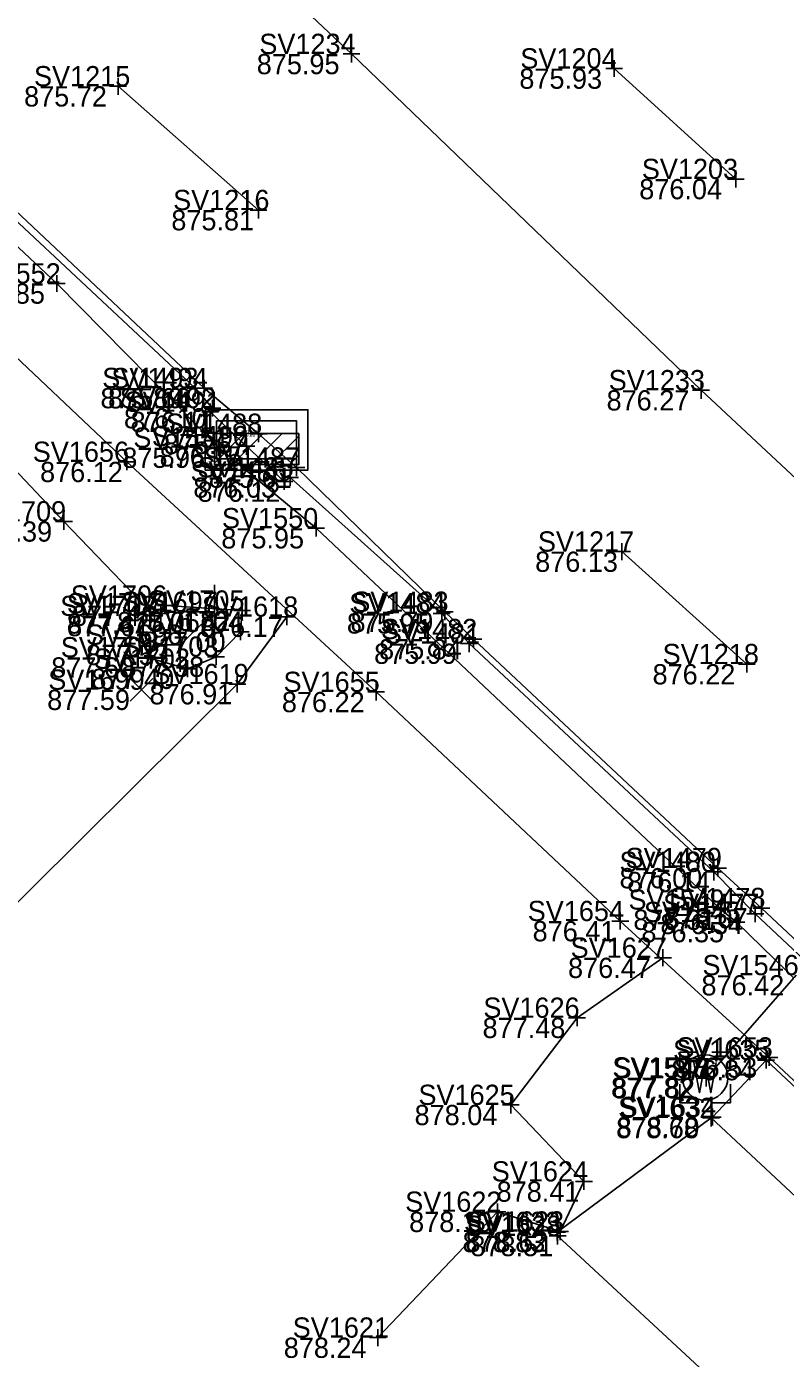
# Model space of a CAD drawing. Extents: x 1480001 to 1480402, y 379235 to 379603.
# Drawn here: x 1480223.3 to 1480268.3, y 379281.8 to 379360.8 of the extents above; entities that cross this region are included whole.
import ezdxf

# ---------------------------------------------------------------- set-up
doc = ezdxf.new("R2010")
doc.units = 0
for name, color, linetype in [('BD_X_Building', 7, 'Continuous'), ('Default', 7, 'Continuous'), ('DR_X_Cells', 7, 'Continuous'), ('GK_Drainage_Nodes', 7, 'Continuous'), ('PM_P_CL_Double_Solid', 7, 'Continuous'), ('PM_X_Lane_Line', 7, 'Continuous'), ('PV_X_Curb', 7, 'Continuous'), ('PV_X_Driveway', 7, 'Continuous'), ('PV_X_Steps', 7, 'Continuous'), ('PV_X_Walk', 7, 'Continuous'), ('RD_X_Concrete_Pad', 7, 'Continuous'), ('SN_X_Public', 7, 'Continuous'), ('SV_X_Break_Lines', 7, 'Continuous'), ('SV_X_Random_Point', 7, 'Continuous'), ('SV_X_Shot_Marker', 7, 'Continuous'), ('SV_X_Text_Elevation', 7, 'Continuous'), ('SV_X_Text_Name', 7, 'Continuous'), ('UT_X_Water', 7, 'Continuous'), ('UT_X_Water_Cells', 7, 'Continuous'), ('VG_X_Flower_Bed', 7, 'Continuous')]:
    doc.layers.add(name, color=color, linetype=linetype)

msp = doc.modelspace()

# ---------------------------------------------------------------- linework, layer by layer
at = {"layer": 'BD_X_Building'}
msp.add_line((1480254.792, 379289.106), (1480285.841, 379260.341), dxfattribs=at)
at = {"layer": 'Default'}
msp.add_line((1480232.416, 379324.173), (1480234.446, 379326.119), dxfattribs=at)
at = {"layer": 'DR_X_Cells'}
for p, q in [((1480234.44, 379334.939), (1480236.194, 379336.697)), ((1480234.44, 379336.071), (1480235.064, 379336.697)), ((1480235.496, 379334.864), (1480237.324, 379336.697)), ((1480236.625, 379334.864), (1480238.454, 379336.697)), ((1480237.755, 379334.864), (1480239.44, 379336.553)), ((1480238.885, 379334.864), (1480239.44, 379335.42))]:
    msp.add_line(p, q, dxfattribs=at)
for points in [[(1480233.898, 379338.115), (1480239.982, 379338.115), (1480239.982, 379334.531), (1480233.898, 379334.531)], [(1480234.44, 379336.697), (1480239.44, 379336.697), (1480239.44, 379334.864), (1480234.44, 379334.864)], [(1480234.565, 379337.447), (1480239.315, 379337.447), (1480239.315, 379335.197), (1480234.565, 379335.197)]]:
    msp.add_lwpolyline(points, close=True, dxfattribs=at)
at = {"layer": 'GK_Drainage_Nodes'}
for p, q in [((1480236.94, 379338.114), (1480236.94, 379338.114)), ((1480236.94, 379337.447), (1480236.94, 379337.447)), ((1480236.94, 379336.697), (1480236.94, 379336.697)), ((1480236.94, 379336.697), (1480236.94, 379336.697)), ((1480234.565, 379336.322), (1480234.565, 379336.322)), ((1480236.94, 379336.322), (1480236.94, 379336.322)), ((1480239.315, 379336.322), (1480239.315, 379336.322)), ((1480236.94, 379335.197), (1480236.94, 379335.197)), ((1480236.94, 379334.531), (1480236.94, 379334.531))]:
    msp.add_line(p, q, dxfattribs=at)
at = {"layer": 'PM_P_CL_Double_Solid'}
msp.add_lwpolyline([(1480349.171, 379259.048), (1480326.954, 379280.06), (1480305.568, 379299.916), (1480284.393, 379319.578), (1480263.301, 379339.268), (1480242.575, 379359.213), (1480224.612, 379376.165), (1480208.191, 379391.527)], dxfattribs=at)
at = {"layer": 'PM_X_Lane_Line'}
for p, q in [((1480265.361, 379351.797), (1480258.147, 379358.351)), ((1480228.73, 379357.297), (1480237.057, 379349.954)), ((1480258.612, 379329.697), (1480266.018, 379323.022))]:
    msp.add_line(p, q, dxfattribs=at)
at = {"layer": 'PV_X_Curb'}
for points in [[(1480332.565, 379246.096), (1480328.494, 379249.894), (1480327.862, 379250.385), (1480312.733, 379264.825), (1480299.577, 379277.28), (1480299.42, 379277.447), (1480285.033, 379290.826), (1480266.518, 379308.208), (1480264.058, 379310.698), (1480249.543, 379324.24), (1480247.919, 379326.036), (1480238.925, 379334.096), (1480238.586, 379333.852), (1480236.341, 379335.947), (1480234.187, 379337.989), (1480234.328, 379338.207), (1480233.297, 379339.4), (1480215.447, 379356.074)], [(1480332.882, 379246.442), (1480328.343, 379250.587), (1480312.97, 379265.236), (1480299.564, 379277.688), (1480285.409, 379291.203), (1480266.888, 379308.553), (1480264.304, 379310.926), (1480249.8, 379324.506), (1480248.109, 379326.126), (1480239.302, 379334.68), (1480237.065, 379336.683), (1480233.83, 379339.39), (1480215.875, 379356.288)]]:
    msp.add_lwpolyline(points, dxfattribs=at)
at = {"layer": 'PV_X_Driveway'}
for points in [[(1480238.736, 379325.837), (1480235.8, 379321.837), (1480220.406, 379306.568)], [(1480244.129, 379283.073), (1480251.224, 379290.538), (1480254.948, 379289.364), (1480256.356, 379292.337), (1480252.019, 379296.878), (1480255.946, 379302.046), (1480261.043, 379305.607)]]:
    msp.add_lwpolyline(points, dxfattribs=at)
at = {"layer": 'PV_X_Steps'}
msp.add_lwpolyline([(1480263.984, 379296.161), (1480267.157, 379299.539), (1480279.089, 379288.407), (1480275.743, 379285.025)], dxfattribs=at)
at = {"layer": 'PV_X_Walk'}
msp.add_lwpolyline([(1480327.959, 379242.083), (1480313.163, 379256.356), (1480297.576, 379270.674), (1480283.951, 379284.205), (1480267.344, 379299.69), (1480258.509, 379307.782), (1480244.036, 379321.372), (1480229.243, 379335.021), (1480213.414, 379349.982), (1480196.806, 379366.202), (1480192.296, 379370.271), (1480186.385, 379375.802), (1480181.8, 379379.27), (1480179.258, 379381.212), (1480177.445, 379382.131), (1480174.921, 379382.868), (1480171.98, 379383.537), (1480169.491, 379383.403), (1480167.014, 379382.902), (1480162.891, 379380.83), (1480161.298, 379379.691), (1480158.915, 379377.808)], dxfattribs=at)
at = {"layer": 'RD_X_Concrete_Pad'}
msp.add_lwpolyline([(1480285.873, 379260.463), (1480292.461, 379269.459), (1480263.894, 379296.102), (1480254.759, 379289.34)], dxfattribs=at)
at = {"layer": 'SN_X_Public'}
for p, q in [((1480234.446, 379327.719), (1480234.446, 379324.519)), ((1480232.416, 379325.773), (1480232.416, 379322.573)), ((1480234.446, 379326.119), (1480232.846, 379326.119)), ((1480232.416, 379324.173), (1480230.816, 379324.173))]:
    msp.add_line(p, q, dxfattribs=at)
at = {"layer": 'SV_X_Break_Lines'}
msp.add_lwpolyline([(1480230.882, 379325.878), (1480225.522, 379331.489), (1480218.264, 379339.152), (1480211.865, 379343.732), (1480205.22, 379349.624), (1480204.187, 379352.051), (1480200.993, 379355.729), (1480195.628, 379356.44), (1480192.91, 379360.091)], dxfattribs=at)
at = {"layer": 'SV_X_Random_Point'}
for p, q in [((1480229.449, 379320.836), (1480230.783, 379322.171)), ((1480229.449, 379322.171), (1480230.783, 379320.836))]:
    msp.add_line(p, q, dxfattribs=at)
at = {"layer": 'SV_X_Shot_Marker'}
for p, q in [((1480242.575, 379359.713), (1480242.575, 379358.713)), ((1480242.075, 379359.213), (1480243.075, 379359.213)), ((1480242.575, 379359.213), (1480242.575, 379359.213)), ((1480258.147, 379358.851), (1480258.147, 379357.851)), ((1480257.647, 379358.351), (1480258.647, 379358.351)), ((1480258.147, 379358.351), (1480258.147, 379358.351)), ((1480228.23, 379357.297), (1480229.23, 379357.297)), ((1480228.73, 379357.797), (1480228.73, 379356.797)), ((1480228.73, 379357.297), (1480228.73, 379357.297)), ((1480264.861, 379351.797), (1480265.861, 379351.797)), ((1480265.361, 379352.297), (1480265.361, 379351.297)), ((1480265.361, 379351.797), (1480265.361, 379351.797)), ((1480237.057, 379350.454), (1480237.057, 379349.454)), ((1480236.557, 379349.954), (1480237.557, 379349.954)), ((1480237.057, 379349.954), (1480237.057, 379349.954)), ((1480224.588, 379345.601), (1480225.588, 379345.601)), ((1480225.088, 379346.101), (1480225.088, 379345.101)), ((1480225.088, 379345.601), (1480225.088, 379345.601)), ((1480233.297, 379339.9), (1480233.297, 379338.9)), ((1480233.83, 379339.89), (1480233.83, 379338.89)), ((1480232.797, 379339.4), (1480233.797, 379339.4)), ((1480233.297, 379339.4), (1480233.297, 379339.4)), ((1480233.33, 379339.39), (1480234.33, 379339.39)), ((1480233.83, 379339.39), (1480233.83, 379339.39)), ((1480262.801, 379339.268), (1480263.801, 379339.268)), ((1480263.301, 379339.768), (1480263.301, 379338.768)), ((1480263.301, 379339.268), (1480263.301, 379339.268)), ((1480234.187, 379338.489), (1480234.187, 379337.489)), ((1480234.328, 379338.707), (1480234.328, 379337.707)), ((1480233.687, 379337.989), (1480234.687, 379337.989)), ((1480233.828, 379338.207), (1480234.828, 379338.207)), ((1480234.187, 379337.989), (1480234.187, 379337.989)), ((1480234.328, 379338.207), (1480234.328, 379338.207)), ((1480236.565, 379336.683), (1480237.565, 379336.683)), ((1480237.065, 379337.183), (1480237.065, 379336.183)), ((1480237.065, 379336.683), (1480237.065, 379336.683)), ((1480234.677, 379336.363), (1480234.677, 379335.363)), ((1480235.841, 379335.947), (1480236.841, 379335.947)), ((1480236.341, 379336.447), (1480236.341, 379335.447)), ((1480236.341, 379335.947), (1480236.341, 379335.947)), ((1480229.243, 379335.521), (1480229.243, 379334.521)), ((1480234.177, 379335.863), (1480235.177, 379335.863)), ((1480234.677, 379335.863), (1480234.677, 379335.863)), ((1480239.302, 379335.18), (1480239.302, 379334.18)), ((1480228.743, 379335.021), (1480229.743, 379335.021)), ((1480229.243, 379335.021), (1480229.243, 379335.021)), ((1480238.586, 379334.352), (1480238.586, 379333.352)), ((1480238.802, 379334.68), (1480239.802, 379334.68)), ((1480238.925, 379334.596), (1480238.925, 379333.596)), ((1480239.302, 379334.68), (1480239.302, 379334.68)), ((1480238.086, 379333.852), (1480239.086, 379333.852)), ((1480238.425, 379334.096), (1480239.425, 379334.096)), ((1480238.586, 379333.852), (1480238.586, 379333.852)), ((1480238.925, 379334.096), (1480238.925, 379334.096)), ((1480225.522, 379331.989), (1480225.522, 379330.989)), ((1480225.022, 379331.489), (1480226.022, 379331.489)), ((1480225.522, 379331.489), (1480225.522, 379331.489)), ((1480240.472, 379331.584), (1480240.472, 379330.584)), ((1480239.972, 379331.084), (1480240.972, 379331.084)), ((1480240.472, 379331.084), (1480240.472, 379331.084)), ((1480258.112, 379329.697), (1480259.112, 379329.697)), ((1480258.612, 379330.197), (1480258.612, 379329.197)), ((1480258.612, 379329.697), (1480258.612, 379329.697)), ((1480231.071, 379326.493), (1480232.071, 379326.493)), ((1480231.266, 379326.534), (1480231.266, 379325.534)), ((1480231.571, 379326.993), (1480231.571, 379325.993)), ((1480231.571, 379326.493), (1480231.571, 379326.493)), ((1480236.086, 379326.695), (1480236.086, 379325.695)), ((1480247.919, 379326.536), (1480247.919, 379325.536)), ((1480248.109, 379326.626), (1480248.109, 379325.626)), ((1480230.382, 379325.878), (1480231.382, 379325.878)), ((1480230.766, 379326.034), (1480231.766, 379326.034)), ((1480230.882, 379326.378), (1480230.882, 379325.378)), ((1480230.882, 379325.878), (1480230.882, 379325.878)), ((1480231.266, 379326.034), (1480231.266, 379326.034)), ((1480235.586, 379326.195), (1480236.586, 379326.195)), ((1480236.086, 379326.195), (1480236.086, 379326.195)), ((1480238.236, 379325.837), (1480239.236, 379325.837)), ((1480238.736, 379326.337), (1480238.736, 379325.337)), ((1480238.736, 379325.837), (1480238.736, 379325.837)), ((1480247.419, 379326.036), (1480248.419, 379326.036)), ((1480247.609, 379326.126), (1480248.609, 379326.126)), ((1480247.919, 379326.036), (1480247.919, 379326.036)), ((1480248.109, 379326.126), (1480248.109, 379326.126)), ((1480235.498, 379324.944), (1480236.498, 379324.944)), ((1480235.998, 379325.444), (1480235.998, 379324.444)), ((1480235.998, 379324.944), (1480235.998, 379324.944)), ((1480249.8, 379325.006), (1480249.8, 379324.006)), ((1480249.043, 379324.24), (1480250.043, 379324.24)), ((1480249.3, 379324.506), (1480250.3, 379324.506)), ((1480249.543, 379324.74), (1480249.543, 379323.74)), ((1480249.543, 379324.24), (1480249.543, 379324.24)), ((1480249.8, 379324.506), (1480249.8, 379324.506)), ((1480229.97, 379323.426), (1480230.97, 379323.426)), ((1480230.47, 379323.926), (1480230.47, 379322.926)), ((1480230.47, 379323.426), (1480230.47, 379323.426)), ((1480232.842, 379323.25), (1480232.842, 379322.25)), ((1480234.041, 379323.463), (1480235.041, 379323.463)), ((1480234.541, 379323.963), (1480234.541, 379322.963)), ((1480234.541, 379323.463), (1480234.541, 379323.463)), ((1480266.018, 379323.522), (1480266.018, 379322.522)), ((1480232.342, 379322.75), (1480233.342, 379322.75)), ((1480232.842, 379322.75), (1480232.842, 379322.75)), ((1480265.518, 379323.022), (1480266.518, 379323.022)), ((1480266.018, 379323.022), (1480266.018, 379323.022)), ((1480235.3, 379321.837), (1480236.3, 379321.837)), ((1480235.8, 379322.337), (1480235.8, 379321.337)), ((1480235.8, 379321.837), (1480235.8, 379321.837)), ((1480244.036, 379321.872), (1480244.036, 379320.872)), ((1480243.536, 379321.372), (1480244.536, 379321.372)), ((1480244.036, 379321.372), (1480244.036, 379321.372)), ((1480264.304, 379311.426), (1480264.304, 379310.426)), ((1480263.558, 379310.698), (1480264.558, 379310.698)), ((1480263.804, 379310.926), (1480264.804, 379310.926)), ((1480264.058, 379311.198), (1480264.058, 379310.198)), ((1480264.058, 379310.698), (1480264.058, 379310.698)), ((1480264.304, 379310.926), (1480264.304, 379310.926)), ((1480266.888, 379309.053), (1480266.888, 379308.053)), ((1480258.509, 379308.282), (1480258.509, 379307.282)), ((1480263.995, 379308.458), (1480264.995, 379308.458)), ((1480264.495, 379308.958), (1480264.495, 379307.958)), ((1480264.495, 379308.458), (1480264.495, 379308.458)), ((1480266.388, 379308.553), (1480267.388, 379308.553)), ((1480266.518, 379308.708), (1480266.518, 379307.708)), ((1480266.888, 379308.553), (1480266.888, 379308.553)), ((1480258.009, 379307.782), (1480259.009, 379307.782)), ((1480258.509, 379307.782), (1480258.509, 379307.782)), ((1480264.901, 379307.725), (1480265.901, 379307.725)), ((1480265.401, 379308.225), (1480265.401, 379307.225)), ((1480265.401, 379307.725), (1480265.401, 379307.725)), ((1480266.018, 379308.208), (1480267.018, 379308.208)), ((1480266.518, 379308.208), (1480266.518, 379308.208)), ((1480261.043, 379306.107), (1480261.043, 379305.107)), ((1480260.543, 379305.607), (1480261.543, 379305.607)), ((1480261.043, 379305.607), (1480261.043, 379305.607)), ((1480255.446, 379302.046), (1480256.446, 379302.046)), ((1480255.946, 379302.546), (1480255.946, 379301.546)), ((1480255.946, 379302.046), (1480255.946, 379302.046)), ((1480266.844, 379299.69), (1480267.844, 379299.69)), ((1480267.157, 379300.039), (1480267.157, 379299.039)), ((1480267.344, 379300.19), (1480267.344, 379299.19)), ((1480267.344, 379299.69), (1480267.344, 379299.69)), ((1480263.602, 379298.962), (1480263.602, 379297.962)), ((1480266.657, 379299.539), (1480267.657, 379299.539)), ((1480267.157, 379299.539), (1480267.157, 379299.539)), ((1480263.102, 379298.462), (1480264.102, 379298.462)), ((1480263.602, 379298.462), (1480263.602, 379298.462)), ((1480252.019, 379297.378), (1480252.019, 379296.378)), ((1480251.519, 379296.878), (1480252.519, 379296.878)), ((1480252.019, 379296.878), (1480252.019, 379296.878)), ((1480263.894, 379296.602), (1480263.894, 379295.602)), ((1480263.984, 379296.661), (1480263.984, 379295.661)), ((1480263.394, 379296.102), (1480264.394, 379296.102)), ((1480263.484, 379296.161), (1480264.484, 379296.161)), ((1480263.894, 379296.102), (1480263.894, 379296.102)), ((1480263.984, 379296.161), (1480263.984, 379296.161)), ((1480256.356, 379292.837), (1480256.356, 379291.837)), ((1480255.856, 379292.337), (1480256.856, 379292.337)), ((1480256.356, 379292.337), (1480256.356, 379292.337)), ((1480251.224, 379291.038), (1480251.224, 379290.038)), ((1480250.724, 379290.538), (1480251.724, 379290.538)), ((1480251.224, 379290.538), (1480251.224, 379290.538)), ((1480254.259, 379289.34), (1480255.259, 379289.34)), ((1480254.448, 379289.364), (1480255.448, 379289.364)), ((1480254.759, 379289.84), (1480254.759, 379288.84)), ((1480254.759, 379289.34), (1480254.759, 379289.34)), ((1480254.792, 379289.606), (1480254.792, 379288.606)), ((1480254.948, 379289.864), (1480254.948, 379288.864)), ((1480254.948, 379289.364), (1480254.948, 379289.364)), ((1480254.292, 379289.106), (1480255.292, 379289.106)), ((1480254.792, 379289.106), (1480254.792, 379289.106)), ((1480243.629, 379283.073), (1480244.629, 379283.073)), ((1480244.129, 379283.573), (1480244.129, 379282.573)), ((1480244.129, 379283.073), (1480244.129, 379283.073))]:
    msp.add_line(p, q, dxfattribs=at)
at = {"layer": 'UT_X_Water'}
msp.add_line((1480268.947, 379304.572), (1480263.602, 379298.462), dxfattribs=at)
msp.add_lwpolyline([(1480327.263, 379249.797), (1480312.798, 379263.799), (1480291.915, 379283.182), (1480274.385, 379298.987), (1480265.401, 379307.725), (1480264.495, 379308.458), (1480240.472, 379331.084), (1480234.677, 379335.863), (1480225.088, 379345.601), (1480208.322, 379361.342)], dxfattribs=at)
at = {"layer": 'UT_X_Water_Cells'}
msp.add_line((1480263.538, 379298.503), (1480263.538, 379298.503), dxfattribs=at)
for points in [[(1480263.138, 379300.003), (1480262.038, 379300.003), (1480262.038, 379298.903)], [(1480265.038, 379298.903), (1480265.038, 379300.003), (1480263.938, 379300.003)], [(1480262.871, 379299.403), (1480263.205, 379297.603), (1480263.538, 379299.403), (1480263.871, 379297.603), (1480264.205, 379299.403)], [(1480262.038, 379298.103), (1480262.038, 379297.003), (1480263.138, 379297.003)], [(1480263.938, 379297.003), (1480265.038, 379297.003), (1480265.038, 379298.103)]]:
    msp.add_lwpolyline(points, dxfattribs=at)
msp.add_circle((1480263.538, 379298.503), 1.35, dxfattribs=at)
at = {"layer": 'VG_X_Flower_Bed'}
msp.add_lwpolyline([(1480230.47, 379323.426), (1480232.842, 379322.75), (1480234.541, 379323.463), (1480235.998, 379324.944), (1480236.086, 379326.195), (1480231.571, 379326.493), (1480231.266, 379326.034)], dxfattribs=at)

# ---------------------------------------------------------------- texts
at = {"layer": 'SV_X_Text_Elevation'}
for s, height, p in [('875.95', 1.2, (1480236.953, 379358.013)), ('875.93', 1.2, (1480252.525, 379357.151)), ('875.72', 1.2, (1480223.156, 379356.097)), ('876.04', 1.2, (1480259.635, 379350.597)), ('875.81', 1.2, (1480231.888, 379348.754)), ('875.85', 1.2, (1480219.485, 379344.401)), ('875.89', 1.2, (1480227.685, 379338.2)), ('875.66', 1.2, (1480228.133, 379338.19)), ('876.27', 1.2, (1480257.698, 379338.068)), ('876.10', 1.2, (1480229.075, 379337.007)), ('876.11', 1.2, (1480229.472, 379336.789)), ('875.67', 1.2, (1480231.443, 379335.483)), ('875.65', 0.2, (1480236.003, 379336.497)), ('875.96', 1.2, (1480228.98, 379334.663)), ('876.15', 1.2, (1480231.192, 379334.747)), ('876.12', 1.2, (1480224.104, 379333.821)), ('875.61', 1.2, (1480234.114, 379333.48)), ('876.03', 1.2, (1480233.19, 379332.896)), ('876.12', 1.2, (1480233.447, 379332.652)), ('877.39', 1.2, (1480219.91, 379330.289)), ('875.95', 1.2, (1480234.85, 379329.884)), ('876.13', 1.2, (1480253.463, 379328.497)), ('877.44', 1.2, (1480225.987, 379325.293)), ('877.42', 1.2, (1480225.682, 379324.834)), ('877.61', 1.2, (1480225.713, 379324.678)), ('877.06', 1.2, (1480228.673, 379324.919)), ('876.82', 1.2, (1480230.474, 379324.995)), ('876.17', 1.2, (1480233.587, 379324.637)), ('875.95', 1.2, (1480242.297, 379324.836)), ('875.79', 1.2, (1480242.516, 379324.926)), ('877.00', 1.2, (1480230.197, 379323.744)), ('877.53', 1.2, (1480226.832, 379322.973)), ('875.99', 1.2, (1480243.912, 379323.04)), ('875.84', 1.2, (1480244.207, 379323.306)), ('877.60', 1.2, (1480224.763, 379322.226)), ('877.38', 1.2, (1480228.929, 379322.263)), ('877.40', 1.2, (1480227.145, 379321.55)), ('876.22', 1.2, (1480260.425, 379321.822)), ('876.91', 1.2, (1480230.593, 379320.637)), ('877.59', 1.2, (1480224.523, 379320.303)), ('876.22', 1.2, (1480238.443, 379320.172)), ('876.00', 1.2, (1480258.465, 379309.726)), ('876.14', 1.2, (1480258.919, 379309.498)), ('876.31', 1.2, (1480259.288, 379307.258)), ('876.07', 1.2, (1480261.153, 379307.353)), ('876.41', 1.2, (1480253.312, 379306.582)), ('876.35', 1.2, (1480259.76, 379306.525)), ('876.34', 1.2, (1480260.887, 379307.008)), ('876.47', 1.2, (1480255.412, 379304.407)), ('876.42', 1.2, (1480263.325, 379303.372)), ('877.48', 1.2, (1480250.343, 379300.846)), ('876.84', 1.2, (1480261.545, 379298.339)), ('876.53', 1.2, (1480261.722, 379298.49)), ('877.82', 1.2, (1480257.964, 379297.303)), ('877.82', 1.2, (1480258.028, 379297.262)), ('878.04', 1.2, (1480246.312, 379295.678)), ('878.68', 1.2, (1480258.263, 379294.902)), ('878.70', 1.2, (1480258.296, 379294.961)), ('878.41', 1.2, (1480251.178, 379291.137)), ('878.10', 1.2, (1480245.99, 379289.338)), ('878.83', 1.2, (1480249.156, 379288.14)), ('878.62', 1.2, (1480249.336, 379288.164)), ('878.51', 1.2, (1480249.623, 379287.906)), ('878.24', 1.2, (1480238.555, 379281.873))]:
    msp.add_text(s, height=height, dxfattribs=at).set_placement(p)
at = {"layer": 'SV_X_Text_Name'}
for s, height, p in [('SV1234', 1.2, (1480237.105, 379359.213)), ('SV1204', 1.2, (1480252.583, 379358.351)), ('SV1215', 1.2, (1480223.743, 379357.297)), ('SV1203', 1.2, (1480259.787, 379351.797)), ('SV1216', 1.2, (1480231.994, 379349.954)), ('SV1552', 1.2, (1480219.618, 379345.601)), ('SV1493', 1.2, (1480227.789, 379339.4)), ('SV1494', 1.2, (1480228.332, 379339.39)), ('SV1233', 1.2, (1480257.822, 379339.268)), ('SV1492', 1.2, (1480228.83, 379338.207)), ('SV1491', 1.2, (1480229.113, 379337.989)), ('SV1488', 1.2, (1480231.567, 379336.683)), ('SV1551', 1.2, (1480229.632, 379335.863)), ('SV1490', 1.2, (1480230.729, 379335.947)), ('SV1489', 0.2, (1480236.024, 379336.697)), ('SV1656', 1.2, (1480223.669, 379335.021)), ('SV1487', 1.2, (1480233.813, 379334.68)), ('SV1485', 1.2, (1480233.436, 379334.096)), ('SV1486', 1.2, (1480233.022, 379333.852)), ('SV1709', 1.2, (1480219.939, 379331.489)), ('SV1550', 1.2, (1480234.889, 379331.084)), ('SV1217', 1.2, (1480253.625, 379329.697)), ('SV1707', 1.2, (1480225.692, 379326.034)), ('SV1706', 1.2, (1480225.922, 379326.493)), ('SV1697', 1.2, (1480228.929, 379326.119)), ('SV1705', 1.2, (1480230.512, 379326.195)), ('SV1484', 1.2, (1480242.44, 379326.036)), ('SV1483', 1.2, (1480242.62, 379326.126)), ('SV1708', 1.2, (1480225.299, 379325.878)), ('SV1618', 1.2, (1480233.701, 379325.837)), ('SV1704', 1.2, (1480230.434, 379324.944)), ('SV1482', 1.2, (1480244.321, 379324.506)), ('SV1696', 1.2, (1480226.823, 379324.173)), ('SV1481', 1.2, (1480244.488, 379324.24)), ('SV1701', 1.2, (1480225.33, 379323.426)), ('SV1703', 1.2, (1480228.967, 379323.463)), ('SV1218', 1.2, (1480261.021, 379323.022)), ('SV1702', 1.2, (1480227.278, 379322.75)), ('SV1699', 1.2, (1480224.589, 379321.503)), ('SV1619', 1.2, (1480230.765, 379321.837)), ('SV1655', 1.2, (1480238.538, 379321.372)), ('SV1480', 1.2, (1480258.465, 379310.698)), ('SV1479', 1.2, (1480258.825, 379310.926)), ('SV1549', 1.2, (1480258.997, 379308.458)), ('SV1477', 1.2, (1480261.048, 379308.208)), ('SV1478', 1.2, (1480261.409, 379308.553)), ('SV1654', 1.2, (1480253.02, 379307.782)), ('SV1545', 1.2, (1480259.912, 379307.725)), ('SV1627', 1.2, (1480255.564, 379305.607)), ('SV1546', 1.2, (1480263.383, 379304.572)), ('SV1626', 1.2, (1480250.391, 379302.046)), ('SV1635', 1.2, (1480261.64, 379299.539)), ('SV1653', 1.2, (1480261.846, 379299.69)), ('SV1548', 1.2, (1480258.04, 379298.503)), ('SV1547', 1.2, (1480258.113, 379298.462)), ('SV1625', 1.2, (1480246.54, 379296.878)), ('SV1632', 1.2, (1480258.386, 379296.102)), ('SV1634', 1.2, (1480258.476, 379296.161)), ('SV1624', 1.2, (1480250.886, 379292.337)), ('SV1622', 1.2, (1480245.754, 379290.538)), ('SV1633', 1.2, (1480249.242, 379289.34)), ('SV1628', 1.2, (1480249.303, 379289.106)), ('SV1623', 1.2, (1480249.469, 379289.364)), ('SV1621', 1.2, (1480239.084, 379283.073))]:
    msp.add_text(s, height=height, dxfattribs=at).set_placement(p)

doc.saveas('drawing.dxf')
